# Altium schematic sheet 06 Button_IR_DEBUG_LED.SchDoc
size 420 x 297 mm
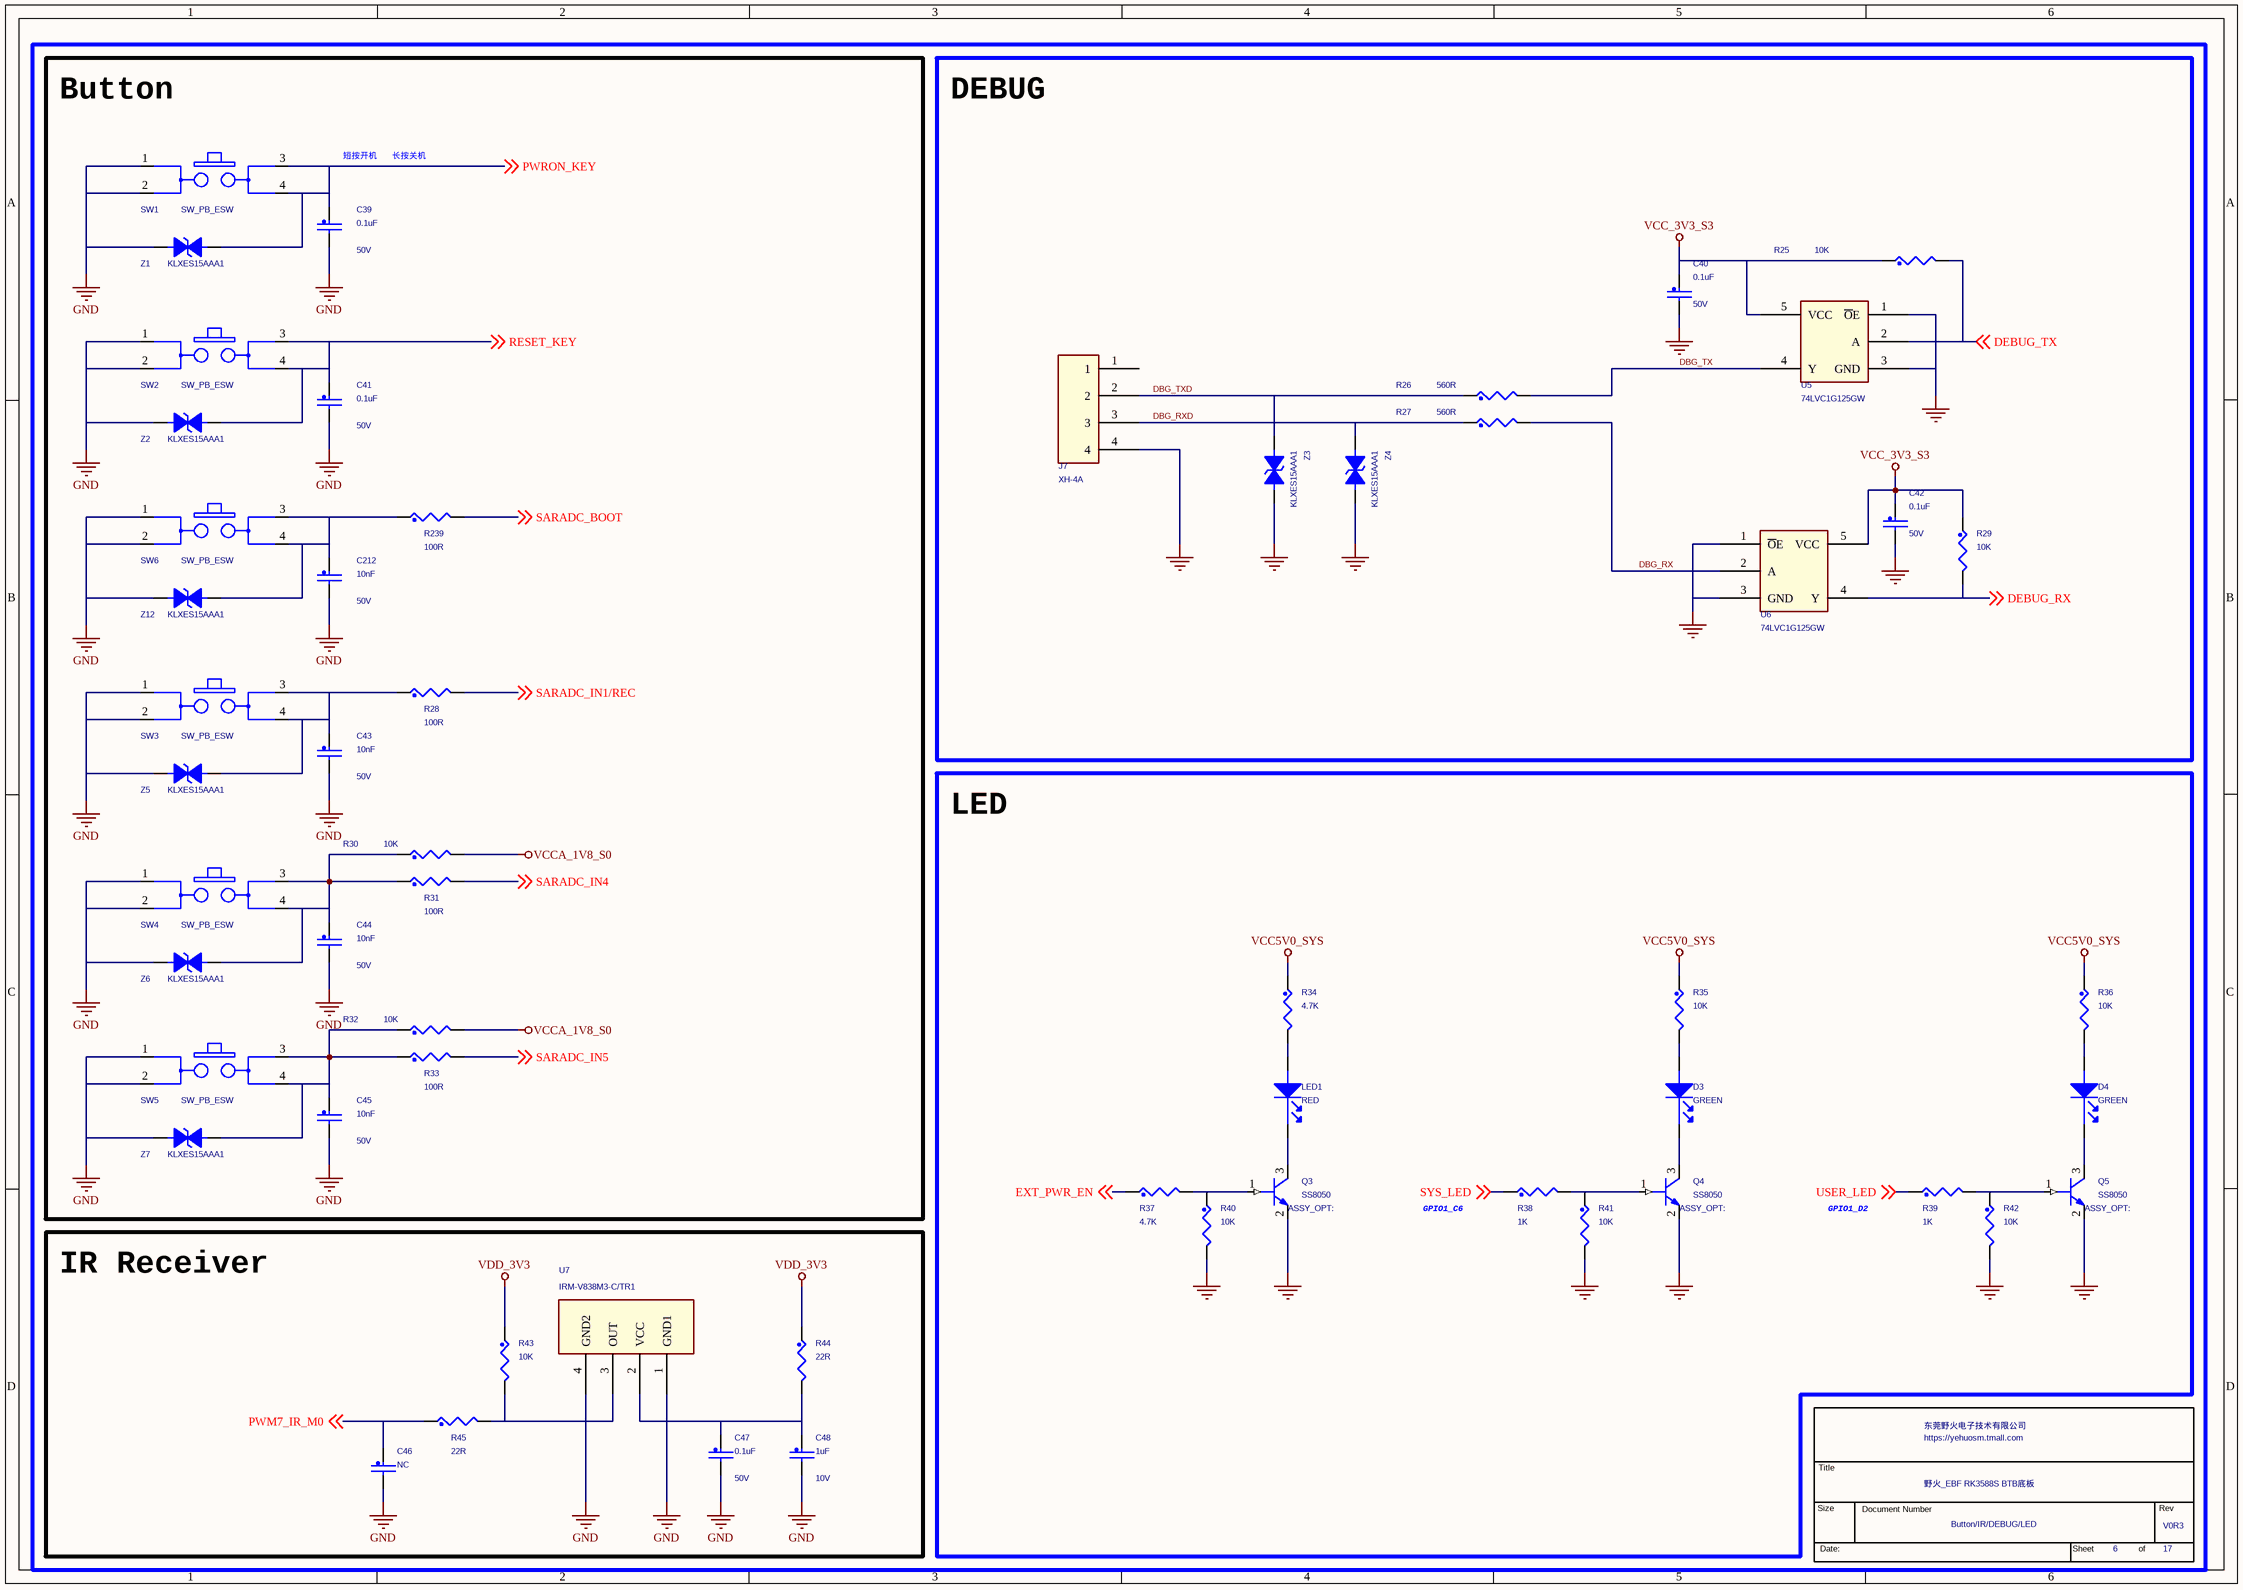
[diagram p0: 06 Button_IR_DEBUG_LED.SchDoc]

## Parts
*  Page Count: 17  Page Number: 6  OrgName: 东莞野火电子技术有限公司  Title: 野火_EBF RK3588S BTB底板  RevCode: V0R3  Doc: Button/IR/DEBUG/LED  (hidden comment: TitleBlock_YHSCH)  (graphical)
C39  0.1uF  Voltage: 50V  [C0402]
C40  0.1uF  Voltage: 50V  [C0402]
C41  0.1uF  Voltage: 50V  [C0402]
C42  0.1uF  Voltage: 50V  [C0402]
C43  10nF  Voltage: 50V  [C0402]
C44  10nF  Voltage: 50V  [C0402]
C45  10nF  Voltage: 50V  [C0402]
C46  NC  [C0402]
C47  0.1uF  Voltage: 50V  [C0402]
C48  1uF  Voltage: 10V  [C0402]
C212  10nF  Voltage: 50V  [C0402]
D3  GREEN  [LED0603]
D4  GREEN  [LED0603]
J7  XH-4A  [XH2R54-4P-V]
LED1  RED  [LED0603]
Q3  SS8050  [SOT23]
Q4  SS8050  [SOT23]
Q5  SS8050  [SOT23]
R25  10K  [R0402]
R26  560R  [R0402]
R27  560R  [R0402]
R28  100R  [R0402]
R29  10K  [R0402]
R30  10K  [R0402]
R31  100R  [R0402]
R32  10K  [R0402]
R33  100R  [R0402]
R34  4.7K  [R0402]
R35  10K  [R0402]
R36  10K  [R0402]
R37  4.7K  [R0402]
R38  1K  [R0402]
R39  1K  [R0402]
R40  10K  [R0402]
R41  10K  [R0402]
R42  10K  [R0402]
R43  10K  [R0402]
R44  22R  [R0402]
R45  22R  [R0402]
R239  100R  [R0402]
SW1  SW_PB_ESW  [SW4-4R20X3R25-SM]
SW2  SW_PB_ESW  [SW4-4R20X3R25-SM]
SW3  SW_PB_ESW  [SW4-4R20X3R25-SM]
SW4  SW_PB_ESW  [SW4-4R20X3R25-SM]
SW5  SW_PB_ESW  [SW4-4R20X3R25-SM]
SW6  SW_PB_ESW  [SW4-4R20X3R25-SM]
U5  74LVC1G125GW  [SOT-353]
U6  74LVC1G125GW  [SOT-353]
U7  IRM-V838M3-C/TR1  [SMD4-6R80X2R50]
Z1  KLXES15AAA1  [D0603/SMD]
Z2  KLXES15AAA1  [D0603/SMD]
Z3  KLXES15AAA1  [D0603/SMD]
Z4  KLXES15AAA1  [D0603/SMD]
Z5  KLXES15AAA1  [D0603/SMD]
Z6  KLXES15AAA1  [D0603/SMD]
Z7  KLXES15AAA1  [D0603/SMD]
Z12  KLXES15AAA1  [D0603/SMD]

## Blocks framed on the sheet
Button: C39 C41 C43-C45 C212 R28 R30-R33 R239 SW1-SW6 Z1 Z2 Z5-Z7 Z12
DEBUG: C40 C42 J7 R25-R27 R29 U5 U6 Z3 Z4
LED: D3 D4 LED1 Q3-Q5 R34-R42
IR Receiver: C46-C48 R43-R45 U7

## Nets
GND: C39.2 C40.2 C41.2 C42.2 C43.2 C44.2 C45.2 C46.2 C47.2 C48.2 C212.2 J7.4 Q3.2(EMITTER) Q4.2(EMITTER) Q5.2(EMITTER) R40.2 R41.2 R42.2 SW1.1(A1) SW1.2(A2) SW2.1(A1) SW2.2(A2) SW3.1(A1) SW3.2(A2) SW4.1(A1) SW4.2(A2) SW5.1(A1) SW5.2(A2) SW6.1(A1) SW6.2(A2) U5.1(~{O}E) U5.3(GND) U6.1(~{O}E) U6.3(GND) U7.1(GND1) U7.4(GND2) Z1.1 Z2.1 Z3.2 Z4.2 Z5.1 Z6.1 Z7.1 Z12.1
VCC5V0_SYS: R34.1 R35.1 R36.1
VCC_3V3_S3: C40.1 C42.1 R25.1 R29.1 U5.5(VCC) U6.5(VCC)
VCCA_1V8_S0: R30.2 R32.2
VDD_3V3: R43.1 R44.1
DBG_RX: R27.2 U6.2(A)
DBG_RXD: J7.3 R27.1 Z4.1
DBG_TX: R26.2 U5.4(Y)
DBG_TXD: J7.2 R26.1 Z3.1
DEBUG_RX: R29.2 U6.4(Y) ; off-sheet DEBUG_RX
DEBUG_TX: R25.2 U5.2(A) ; off-sheet DEBUG_TX
EXT_PWR_EN: R37.1 ; off-sheet EXT_PWR_EN
PWM7_IR_M0: C46.1 R45.1 ; off-sheet PWM7_IR_M0
PWRON_KEY: C39.1 SW1.3(B1) SW1.4(B2) Z1.2 ; off-sheet PWRON_KEY
RESET_KEY: C41.1 SW2.3(B1) SW2.4(B2) Z2.2 ; off-sheet RESET_KEY
SARADC_BOOT: R239.2 ; off-sheet SARADC_BOOT
SARADC_IN1/REC: R28.2 ; off-sheet SARADC_IN1/REC
SARADC_IN4: R31.2 ; off-sheet SARADC_IN4
SARADC_IN5: R33.2 ; off-sheet SARADC_IN5
SYS_LED: R38.1 ; off-sheet SYS_LED
USER_LED: R39.1 ; off-sheet USER_LED
NetC43_1: C43.1 R28.1 SW3.3(B1) SW3.4(B2) Z5.2
NetC44_1: C44.1 R30.1 R31.1 SW4.3(B1) SW4.4(B2) Z6.2
NetC45_1: C45.1 R32.1 R33.1 SW5.3(B1) SW5.4(B2) Z7.2
NetC47_1: C47.1 C48.1 R44.2 U7.2(VCC)
NetC212_1: C212.1 R239.1 SW6.3(B1) SW6.4(B2) Z12.2
NetD3_1: D3.1(CATHODE) Q4.3(COLLECTOR)
NetD3_2: D3.2(ANODE) R35.2
NetD4_1: D4.1(CATHODE) Q5.3(COLLECTOR)
NetD4_2: D4.2(ANODE) R36.2
NetLED1_1: LED1.1(CATHODE) Q3.3(COLLECTOR)
NetLED1_2: LED1.2(ANODE) R34.2
NetQ3_1: Q3.1(BASE) R37.2 R40.1
NetQ4_1: Q4.1(BASE) R38.2 R41.1
NetQ5_1: Q5.1(BASE) R39.2 R42.1
NetR43_2: R43.2 R45.2 U7.3(OUT)

Not connected (* = marked no-connect by the designer): J7 1

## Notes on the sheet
- 短按开机   长按关机
- GPIO1_C6
- GPIO1_D2

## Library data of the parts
* = TitleBlock_YHSCH: Cage Code: 1
C39 C40 C47 = CAP_NP: CLASS: DISCRETE; 规格: 贴片电容0.1uF 10% 50V X5R 0402; 规格编号: 0402X104K500NT; 条码: EBF29060118; 品牌: 风华; 类别: 贴片电容0402; 规格书: 风华电容.pdf; 价格: 0.029826; 生命周期: 量产
C41 C42 = CAP_NP: CLASS: DISCRETE; 生命周期: 量产; 价格: 0.029826; 规格书: 风华电容.pdf; 类别: 贴片电容0402; 品牌: 风华; 条码: EBF29060118; 规格编号: 0402X104K500NT; 规格: 贴片电容0.1uF 10% 50V X5R 0402
C43 C44 = CAP_NP: CLASS: DISCRETE; 生命周期: 量产; 价格: 0.003808; 规格书: 国巨-贴片电容.pdf; 类别: 贴片电容0402; 品牌: 国巨; 条码: EBF29060245; 规格编号: CC0402KRX7R9BB103; 规格: 贴片电容10nF 10% 50V X7R 0402
C45 C212 = CAP_NP: CLASS: DISCRETE; 规格: 贴片电容10nF 10% 50V X7R 0402; 规格编号: CC0402KRX7R9BB103; 条码: EBF29060245; 品牌: 国巨; 类别: 贴片电容0402; 规格书: 国巨-贴片电容.pdf; 价格: 0.003808; 生命周期: 量产
C46 = CAP_NP: CLASS: DISCRETE; 类别: 贴片电容0402; 条码: EBF29060149; 规格: 贴片电容NC 预留
C48 = CAP_NP: CLASS: DISCRETE; 规格: 贴片电容1uF 10% 10V X5R 0402; 规格编号: 0402X105K100NT; 条码: EBF29060121; 品牌: 风华; 类别: 贴片电容0402; 规格书: 风华电容.pdf; 价格: 0.01191; 生命周期: 量产
D3 D4 = LED: 规格: 贴片LED GREEN 正向电流20mA 0603 正贴; 规格编号: EL0603/GHC-C01/DT; 条码: EBF29140043; 品牌: 亿光; 类别: 贴片LED; 规格书: LED0603-RED.pdf; 生命周期: 量产
J7 = 1X4PIN: 可替代料: EBF29040012; 生命周期: 量产; 价格: 0.041116; 规格书: 博穆精密-XH2.54.pdf; 类别: XH连接器; 品牌: 博穆精密; 规格: 直针XH2.54-4P 间距2.54MM 拔插式 接插件 直插
LED1 = LED: 规格: 贴片LED RED 正向电流30mA 反向电压9V 功率消耗350mW 0603; 规格编号: 35B00617LGY-RED; 条码: EBF29140007; 品牌: 亿光; 类别: 贴片LED; 规格书: LED0603-RED.pdf; 生命周期: 量产
Q3 = NPN: CLASS: IC; 丝印: Y1; 生命周期: 量产; 价格: 0.086744; 规格书: 江苏长电-SS8050Y1.pdf; 类别: 贴片三极管SOT-23; 品牌: 江苏长电; 条码: EBF29090001; 规格: 贴片三极管SS8050 集电极电流1.5A 额定功率300mW NPN
Q4 Q5 = NPN: CLASS: IC; 规格: 贴片三极管SS8050 集电极电流1.5A 额定功率300mW NPN; 条码: EBF29090001; 品牌: 江苏长电; 类别: 贴片三极管SOT-23; 规格书: 江苏长电-SS8050Y1.pdf; 价格: 0.086744; 生命周期: 量产; 丝印: Y1
R25 R40 R43 = RES: CLASS: DISCRETE; 生命周期: 量产; 价格: 0.002773; 规格书: 厚声-无铅厚膜电阻.pdf; 类别: 贴片电阻0402; 品牌: 厚声; 条码: EBF29070046; 规格编号: 0402WGF1002TCE; 规格: 贴片电阻10K 1% 1/16W 0402
R26 R27 = RES: CLASS: DISCRETE; 价格: 0.002258; 规格: 贴片电阻560R 1% 1/16W 0402; 规格编号: 0402WGF5600TCE; 条码: EBF29070272; 品牌: 厚声; 类别: 贴片电阻0402; 规格书: 厚声-无铅厚膜电阻.pdf; 生命周期: 量产
R28 = RES: CLASS: DISCRETE; 生命周期: 量产; 规格书: 合科泰-RI系列电阻.pdf; 类别: 贴片电阻0402; 品牌: 合科泰; 条码: EBF29070053; 规格编号: RI0402L1000FT; 规格: 贴片电阻100R 1% 1/16W 0402
R29 R41 R42 = RES: CLASS: DISCRETE; 规格: 贴片电阻10K 1% 1/16W 0402; 规格编号: 0402WGF1002TCE; 条码: EBF29070046; 品牌: 厚声; 类别: 贴片电阻0402; 规格书: 厚声-无铅厚膜电阻.pdf; 价格: 0.002773; 生命周期: 量产
R30 R32 = RES: CLASS: DISCRETE; 价格: 0.002773; 规格: 贴片电阻10K 1% 1/16W 0402; 规格编号: 0402WGF1002TCE; 条码: EBF29070046; 品牌: 厚声; 类别: 贴片电阻0402; 规格书: 厚声-无铅厚膜电阻.pdf; 生命周期: 量产
R31 R33 R239 = RES: CLASS: DISCRETE; 规格: 贴片电阻100R 1% 1/16W 0402; 规格编号: RI0402L1000FT; 条码: EBF29070053; 品牌: 合科泰; 类别: 贴片电阻0402; 规格书: 合科泰-RI系列电阻.pdf; 生命周期: 量产
R34 = RES: CLASS: DISCRETE; 生命周期: 量产; 规格书: 合科泰-RI系列电阻.pdf; 类别: 贴片电阻0402; 品牌: 合科泰; 条码: EBF29070047; 规格编号: RI0402L4701FT; 规格: 贴片电阻4.7K 1% 1/16W 0402
R35 R36 = RES: CLASS: DISCRETE; 规格: 贴片电阻10K 1% 1/16W 0402; 规格编号: 0402WGF1002TCE; 条码: EBF29070046; 品牌: 厚声; 类别: 贴片电阻0402; 规格书: 厚声-无铅厚膜电阻.pdf; 生命周期: 量产; 价格: 0.002773
R37 = RES: CLASS: DISCRETE; 规格: 贴片电阻4.7K 1% 1/16W 0402; 规格编号: RI0402L4701FT; 条码: EBF29070047; 品牌: 合科泰; 类别: 贴片电阻0402; 规格书: 合科泰-RI系列电阻.pdf; 生命周期: 量产
R38 R39 = RES: CLASS: DISCRETE; 生命周期: 量产; 规格书: 合科泰-RI系列电阻.pdf; 类别: 贴片电阻0402; 品牌: 合科泰; 条码: EBF29070050; 规格编号: RI0402L1001FT; 规格: 贴片电阻1K 1% 1/16W 0402
R44 R45 = RES: CLASS: DISCRETE; 生命周期: 量产; 规格书: 合科泰-RI系列电阻.pdf; 类别: 贴片电阻0402; 品牌: 合科泰; 条码: EBF29070181; 规格编号: RI0402L22R0FT; 规格: 贴片电阻22R 1% 1/16W 0402
SW1 SW2 SW4 = SW_PB_ESW: CLASS: IC; 生命周期: 量产; 价格: 0.168282; 规格书: 讯普3×4×2.5160GF轻触开.pdf; 类别: 贴片轻触开关; 品牌: 讯普; 条码: EBF29310006; 规格编号: TS-1089U-AR02526; 规格: 3×4×2.5 160gf 轻触开关 白色; 备注: 修正封装
SW3 = SW_PB_ESW: CLASS: IC; 备注: 修正封装; 生命周期: 量产; 价格: 0.168282; 规格书: 讯普3×4×2.5160GF轻触开.pdf; 类别: 贴片轻触开关; 品牌: 讯普; 条码: EBF29310006; 规格编号: TS-1089U-AR02526; 规格: 3×4×2.5 160gf 轻触开关 白色
SW5 SW6 = SW_PB_ESW: CLASS: IC; 规格: 3×4×2.5 160gf 轻触开关 白色; 规格编号: TS-1089U-AR02526; 条码: EBF29310006; 品牌: 讯普; 类别: 贴片轻触开关; 规格书: 讯普3×4×2.5160GF轻触开.pdf; 价格: 0.168282; 生命周期: 量产; 备注: 修正封装
U5 = 74LVC1G125: 规格: 时钟缓冲器 驱动器 具有三态输出 允许工作电压为3.3V 5.5V 典型工作电流100mA; 条码: EBF29170001; 品牌: 安世; 类别: 隔离器件; 规格书: 74LVC1G125GW.pdf; 价格: 0.182409; 生命周期: 量产; 丝印: VM
U6 = 74LVC1G125: 丝印: VM; 生命周期: 量产; 价格: 0.182409; 规格书: 74LVC1G125GW.pdf; 类别: 隔离器件; 品牌: 安世; 条码: EBF29170001; 规格: 时钟缓冲器 驱动器 具有三态输出 允许工作电压为3.3V 5.5V 典型工作电流100mA
U7 = IRM-V838M3-C/TR1: 生命周期: 量产; 规格书: IRM-V838M3-C_TR1.pdf; 类别: 红外接收头; 品牌: 亿光; 条码: EBF29230005; 规格: 侧贴红外遥控接收头 工作电压2.7V~5.5V 兼容TTL与CMOS
Z1 Z3 Z4 Z7 Z12 = DIODE BI-DIR TRIG: 规格: 用于 USB3.0、HDMI 0.5pF、5V、±15kV ESD 保护二极管; 条码: EBF29140063; 品牌: 永裕泰; 类别: 贴片ESD; 规格书: KLXES15AAA1.pdf; 价格: 0.09719; 生命周期: 量产
Z2 Z5 Z6 = DIODE BI-DIR TRIG: 生命周期: 量产; 价格: 0.09719; 规格书: KLXES15AAA1.pdf; 类别: 贴片ESD; 品牌: 永裕泰; 条码: EBF29140063; 规格: 用于 USB3.0、HDMI 0.5pF、5V、±15kV ESD 保护二极管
